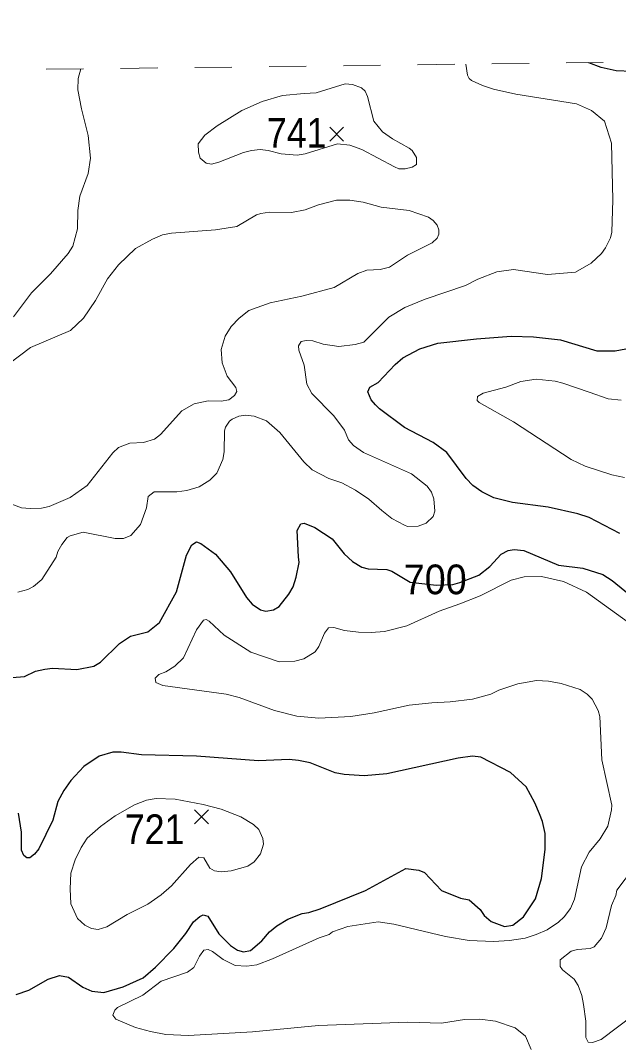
# Model space of a CAD drawing. Extents: x 294.2 to 320.3, y 7482.7 to 7510.7.
# Drawn here: x 309.032 to 310.642, y 7507.992 to 7510.744 of the extents above; entities that cross this region are included whole.
import ezdxf
from ezdxf.enums import TextEntityAlignment as Align

# ---------------------------------------------------------------- set-up
doc = ezdxf.new("R2010")
doc.units = 0
doc.header["$LTSCALE"] = 0.032
doc.linetypes.add('SHORT_DASHED', pattern=[2.7, 1.5, -1.2])
for name, color, linetype, lineweight in [('1', 7, 'Continuous', 25), ('2', 7, 'Continuous', 13), ('21', 7, 'Continuous', 25), ('22', 7, 'SHORT_DASHED', 13)]:
    doc.layers.add(name, color=color, linetype=linetype, lineweight=lineweight)
doc.layers.add('61', color=7, linetype='Continuous')

msp = doc.modelspace()

# ---------------------------------------------------------------- linework, layer by layer
at = {"layer": '1'}
for points in [[(310.7625, 7510.6029), (310.636, 7510.6077), (310.5953, 7510.6168), (310.5623, 7510.63)], [(310.2324, 7509.511), (310.1802, 7509.5804), (310.1436, 7509.6078), (310.066, 7509.6481), (309.9985, 7509.698), (309.9883, 7509.7088), (309.9762, 7509.7222), (309.9677, 7509.7439), (309.973, 7509.7567), (309.9953, 7509.7688), (310.0406, 7509.818), (310.0617, 7509.8359), (310.107, 7509.8601), (310.1562, 7509.8748), (310.2597, 7509.8869), (310.3535, 7509.894), (310.4131, 7509.8922), (310.4858, 7509.8841), (310.5841, 7509.8545), (310.6329, 7509.8545), (310.6623, 7509.8593)], [(310.5325, 7509.4158), (310.4526, 7509.4335), (310.3572, 7509.4459), (310.3062, 7509.4583), (310.274, 7509.4744), (310.2502, 7509.4916), (310.2324, 7509.511)], [(310.6462, 7509.3631), (310.563, 7509.4061), (310.5325, 7509.4158)], [(309.0091, 7508.9747), (309.0429, 7508.978), (309.0723, 7508.9919), (309.0978, 7508.9979), (309.1178, 7509), (309.1838, 7508.9962), (309.2293, 7509.0059), (309.247, 7509.0167), (309.2986, 7509.0667), (309.3286, 7509.086), (309.3751, 7509.0979), (309.4067, 7509.1232), (309.4517, 7509.2059), (309.4788, 7509.3044), (309.4932, 7509.3318), (309.506, 7509.3404), (309.5176, 7509.3361), (309.5575, 7509.307), (309.5974, 7509.2596), (309.6407, 7509.1908), (309.6562, 7509.1725), (309.6779, 7509.1569), (309.6928, 7509.1532), (309.7133, 7509.157), (309.7288, 7509.1666), (309.7549, 7509.1994), (309.7666, 7509.2193), (309.7739, 7509.2448), (309.7822, 7509.2847), (309.781, 7509.2997), (309.7771, 7509.3708), (309.7866, 7509.389), (309.796, 7509.3907), (309.8249, 7509.3788), (309.8709, 7509.348), (309.9037, 7509.3076), (309.9264, 7509.2872), (309.9508, 7509.2721), (309.9685, 7509.2673), (310.0185, 7509.2656), (310.0323, 7509.2613), (310.0811, 7509.2317), (310.1521, 7509.2237), (310.1964, 7509.2258), (310.2147, 7509.2312), (310.2663, 7509.2506), (310.2962, 7509.2737), (310.3261, 7509.307), (310.3456, 7509.3173), (310.3611, 7509.3199), (310.3872, 7509.3167), (310.4805, 7509.2774), (310.546, 7509.2697), (310.6004, 7509.2519), (310.6254, 7509.2358), (310.6935, 7509.1807)], [(309.0204, 7508.1222), (309.0542, 7508.133), (309.1069, 7508.1626), (309.1368, 7508.1733), (309.1612, 7508.1685), (309.1995, 7508.1416), (309.2239, 7508.1303), (309.2561, 7508.1271), (309.3088, 7508.1421), (309.362, 7508.1668), (309.3959, 7508.1953), (309.4447, 7508.2458), (309.4769, 7508.2856), (309.4974, 7508.3173), (309.5146, 7508.3313), (309.524, 7508.3361), (309.5362, 7508.3324), (309.5662, 7508.2851), (309.5972, 7508.2534), (309.6161, 7508.2415), (309.6322, 7508.2362), (309.6516, 7508.2405), (309.6821, 7508.2658), (309.7021, 7508.29), (309.722, 7508.3066), (309.752, 7508.3244), (309.7903, 7508.3395), (309.808, 7508.3421), (309.8385, 7508.3524), (309.9611, 7508.4014), (310.0695, 7508.4607), (310.1045, 7508.4568), (310.12, 7508.4499), (310.1655, 7508.402), (310.2165, 7508.381), (310.2398, 7508.3762), (310.2697, 7508.3509), (310.2808, 7508.3348), (310.2991, 7508.3181), (310.3352, 7508.3052), (310.3579, 7508.3084), (310.3868, 7508.331), (310.4184, 7508.3789), (310.4345, 7508.4343), (310.4451, 7508.5117), (310.4445, 7508.5553), (310.4377, 7508.5878), (310.4299, 7508.6077), (310.4171, 7508.6378), (310.3933, 7508.6809), (310.3512, 7508.7196), (310.2717, 7508.7604), (310.2494, 7508.7631), (310.2106, 7508.7583), (310.0181, 7508.7159), (309.9576, 7508.71), (309.9033, 7508.7138), (309.8789, 7508.7186), (309.8118, 7508.7455), (309.7807, 7508.7514), (309.7552, 7508.7541), (309.6731, 7508.7503), (309.5061, 7508.7632), (309.358, 7508.7669), (309.3031, 7508.7744), (309.2808, 7508.7744), (309.2442, 7508.7632), (309.2021, 7508.7352), (309.1671, 7508.6981), (309.1483, 7508.6712), (309.1328, 7508.6416), (309.1189, 7508.5911), (309.0811, 7508.5142), (309.07, 7508.4992), (309.0573, 7508.49), (309.0489, 7508.49), (309.0406, 7508.4959), (309.0351, 7508.5105), (309.0345, 7508.5584), (309.0262, 7508.61)]]:
    msp.add_lwpolyline(points, dxfattribs=at)
at = {"layer": '2'}
for points in [[(309.0133, 7509.9457), (309.0618, 7510.0108), (309.1129, 7510.0619), (309.1602, 7510.1168), (309.1729, 7510.136), (309.1851, 7510.1826), (309.1864, 7510.2318), (309.1921, 7510.2707), (309.2145, 7510.332), (309.2202, 7510.3729), (309.2145, 7510.4342), (309.1959, 7510.5057), (309.1864, 7510.5567), (309.187, 7510.5874), (309.1942, 7510.6134)], [(310.2314, 7510.626), (310.236, 7510.5963), (310.2405, 7510.5874), (310.2462, 7510.5816), (310.2763, 7510.5689), (310.3056, 7510.5587), (310.3657, 7510.5452), (310.5291, 7510.5191), (310.57, 7510.5012), (310.6044, 7510.4724), (310.623, 7510.4137), (310.6268, 7510.2605), (310.6242, 7510.1737), (310.6204, 7510.1583), (310.6076, 7510.1315), (310.5961, 7510.1162), (310.5687, 7510.09), (310.5265, 7510.0657), (310.4512, 7510.0594), (310.3593, 7510.0734), (310.3146, 7510.067), (310.2635, 7510.0472), (310.2303, 7510.0306), (310.1218, 7509.9936), (310.0668, 7509.9712), (310.0234, 7509.9451), (309.9564, 7509.8774), (309.9328, 7509.871), (309.8894, 7509.8659), (309.8472, 7509.8723), (309.8191, 7509.8812), (309.8012, 7509.8825), (309.7878, 7509.8799), (309.7802, 7509.8678), (309.7814, 7509.8563), (309.7955, 7509.8161), (309.8031, 7509.765), (309.8165, 7509.7395), (309.8759, 7509.6795), (309.904, 7509.6412), (309.9149, 7509.6144), (309.9289, 7509.5996), (309.9558, 7509.5805), (310.0847, 7509.523), (310.1268, 7509.4905), (310.1383, 7509.4739), (310.1454, 7509.456), (310.1479, 7509.4228), (310.1428, 7509.4087), (310.1243, 7509.3902), (310.1026, 7509.3826), (310.0745, 7509.3819), (310.0656, 7509.3851), (310.0317, 7509.403), (310.0049, 7509.4247), (309.9698, 7509.4547), (309.934, 7509.4796), (309.897, 7509.4988), (309.8625, 7509.5103), (309.8178, 7509.5339), (309.7948, 7509.5556), (309.7304, 7509.6341), (309.694, 7509.6661), (309.6608, 7509.6782), (309.6378, 7509.6814), (309.6199, 7509.6788), (309.602, 7509.6705), (309.595, 7509.6654), (309.5841, 7509.6488), (309.581, 7509.6392), (309.5803, 7509.5824), (309.5765, 7509.562), (309.5605, 7509.5249), (309.5414, 7509.5064), (309.5127, 7509.4886), (309.4795, 7509.4783), (309.4526, 7509.4745), (309.3919, 7509.4745), (309.376, 7509.4624), (309.3715, 7509.4317), (309.3549, 7509.3871), (309.3288, 7509.357), (309.309, 7509.3494), (309.2866, 7509.3494), (309.2011, 7509.366), (309.1653, 7509.3564), (309.1576, 7509.3519), (309.1429, 7509.3334), (309.1321, 7509.3142), (309.1276, 7509.2989), (309.0893, 7509.2389), (309.067, 7509.2197), (309.0517, 7509.2115), (309.0249, 7509.2044)], [(308.9687, 7509.7963), (309.0593, 7509.8633), (309.1666, 7509.9093), (309.2017, 7509.9425), (309.2342, 7509.9898), (309.2662, 7510.0478), (309.2955, 7510.0862), (309.3414, 7510.1301), (309.3874, 7510.1551), (309.4143, 7510.1666), (309.4386, 7510.1711), (309.5573, 7510.18), (309.6141, 7510.189), (309.6672, 7510.2202), (309.6787, 7510.2241), (309.7029, 7510.2273), (309.7617, 7510.2266), (309.7987, 7510.2336), (309.8344, 7510.2471), (309.883, 7510.2598), (309.9187, 7510.2598), (309.9545, 7510.2541), (310.003, 7510.2407), (310.0783, 7510.2318), (310.1307, 7510.2139), (310.1435, 7510.2056), (310.1537, 7510.1928), (310.1588, 7510.18), (310.1588, 7510.1685), (310.1543, 7510.1577), (310.1409, 7510.1455), (310.0745, 7510.1117), (310.026, 7510.0798), (310.0005, 7510.0734), (309.9647, 7510.0715), (309.9404, 7510.0625), (309.8766, 7510.0249), (309.7898, 7510.0019), (309.7042, 7509.984), (309.6467, 7509.9629), (309.6206, 7509.9425), (309.5995, 7509.9195), (309.5835, 7509.894), (309.5726, 7509.8583), (309.5746, 7509.8225), (309.5886, 7509.7861), (309.6116, 7509.7561), (309.6148, 7509.7446), (309.6084, 7509.7344), (309.5931, 7509.7229), (309.5727, 7509.719), (309.5369, 7509.7197), (309.4999, 7509.712), (309.4667, 7509.6929), (309.4092, 7509.629), (309.3926, 7509.6169), (309.3633, 7509.6079), (309.3262, 7509.606), (309.2962, 7509.5939), (309.2809, 7509.5799), (309.2113, 7509.4917), (309.1659, 7509.4592), (309.1091, 7509.4355), (309.0887, 7509.4311), (309.0581, 7509.4298), (309.0347, 7509.4317), (309.0088, 7509.442)], [(310.6491, 7509.7216), (310.6147, 7509.7248), (310.5636, 7509.7427), (310.4921, 7509.7676), (310.4716, 7509.7726), (310.4206, 7509.7778), (310.3797, 7509.7714), (310.3388, 7509.7567), (310.2776, 7509.7401), (310.2628, 7509.7312), (310.2616, 7509.7209), (310.2667, 7509.7152), (310.3593, 7509.6635), (310.515, 7509.562), (310.5521, 7509.5435), (310.624, 7509.5205), (310.6581, 7509.5134)], [(310.6696, 7509.1234), (310.5559, 7509.2051), (310.4946, 7509.2332), (310.4346, 7509.2472), (310.3886, 7509.2459), (310.3529, 7509.237), (310.2699, 7509.1949), (310.215, 7509.1732), (310.1594, 7509.1533), (310.072, 7509.1144), (310.0119, 7509.0991), (309.9762, 7509.0959), (309.9417, 7509.0972), (309.9047, 7509.1016), (309.8759, 7509.1093), (309.8612, 7509.1086), (309.8504, 7509.0946), (309.8351, 7509.0589), (309.8255, 7509.0442), (309.7949, 7509.025), (309.7706, 7509.0186), (309.7285, 7509.0174), (309.6518, 7509.0429), (309.5803, 7509.0889), (309.5401, 7509.1265), (309.5318, 7509.131), (309.5247, 7509.1297), (309.5062, 7509.1036), (309.4711, 7509.0282), (309.4475, 7509.0052), (309.4233, 7508.9906), (309.4041, 7508.9829), (309.3945, 7508.9733), (309.3964, 7508.9618), (309.4156, 7508.9535), (309.5854, 7508.9305), (309.6212, 7508.9209), (309.7157, 7508.8864), (309.7757, 7508.8711), (309.8357, 7508.866), (309.9213, 7508.8698), (309.9839, 7508.8795), (310.0783, 7508.9005), (310.1396, 7508.9069), (310.1894, 7508.9094), (310.2495, 7508.9171), (310.2986, 7508.9305), (310.3197, 7508.9408), (310.3708, 7508.958), (310.4218, 7508.9669), (310.4538, 7508.9656), (310.4882, 7508.9592), (310.5387, 7508.9426), (310.5578, 7508.9305), (310.5712, 7508.9171), (310.5872, 7508.8865), (310.5917, 7508.8705), (310.5974, 7508.7537), (310.6243, 7508.6317), (310.6238, 7508.6184), (310.6133, 7508.5749), (310.5929, 7508.5411), (310.5635, 7508.5047), (310.5425, 7508.4651), (310.524, 7508.3783), (310.5131, 7508.3533), (310.4959, 7508.3304), (310.4806, 7508.3169), (310.4499, 7508.2959), (310.4206, 7508.2831), (310.3912, 7508.2735), (310.3491, 7508.2671), (310.3056, 7508.264), (310.2405, 7508.2671), (310.1767, 7508.278), (310.0375, 7508.3112), (309.9949, 7508.3176), (309.9134, 7508.3045), (309.8721, 7508.2901), (309.8629, 7508.2831)], [(310.6836, 7508.0673), (310.5955, 7508.0009), (310.5725, 7507.9926), (310.5604, 7507.9932), (310.554, 7508.006), (310.554, 7508.0501), (310.5482, 7508.0948), (310.5438, 7508.119), (310.5336, 7508.1459), (310.5227, 7508.1631), (310.4914, 7508.1886), (310.485, 7508.1975), (310.485, 7508.2154), (310.5144, 7508.2384), (310.5317, 7508.2429), (310.5661, 7508.2454), (310.577, 7508.2505), (310.5961, 7508.2735), (310.6089, 7508.3016), (310.6236, 7508.361), (310.6351, 7508.3885), (310.6376, 7508.4025), (310.7673, 7508.573)], [(309.8629, 7508.2831), (309.8365, 7508.2742), (309.7106, 7508.218), (309.6684, 7508.202), (309.6416, 7508.1976), (309.61, 7508.2), (309.5778, 7508.2162)], [(309.5778, 7508.2162), (309.5491, 7508.2379), (309.5376, 7508.2429), (309.5261, 7508.241), (309.5139, 7508.225), (309.4986, 7508.1943), (309.482, 7508.1822), (309.4111, 7508.1573), (309.3613, 7508.1196), (309.2931, 7508.0869), (309.2856, 7508.0796), (309.281, 7508.0657), (309.2885, 7508.0552), (309.3415, 7508.0328), (309.3824, 7508.0219), (309.4233, 7508.0143), (309.4846, 7508.0111), (309.657, 7508.0213), (309.8344, 7508.0379), (310.0754, 7508.047), (310.1652, 7508.0449), (310.2278, 7508.0545), (310.2686, 7508.0558), (310.3108, 7508.05), (310.3644, 7508.0316), (310.3918, 7508.0098), (310.4072, 7507.9735)]]:
    msp.add_lwpolyline(points, dxfattribs=at)
for points in [[(309.7961, 7510.5471), (309.7374, 7510.5421), (309.6825, 7510.5255), (309.6276, 7510.5012), (309.5612, 7510.4603), (309.5286, 7510.4348), (309.5107, 7510.4112), (309.5113, 7510.3895), (309.5158, 7510.3729), (309.5318, 7510.3594), (309.5459, 7510.3569), (309.5663, 7510.362), (309.6327, 7510.3881), (309.6544, 7510.3932), (309.6774, 7510.3965), (309.6991, 7510.3939), (309.7336, 7510.3843), (309.777, 7510.3812), (309.7987, 7510.385), (309.8855, 7510.4118), (309.9189, 7510.4081), (309.9507, 7510.3965), (310.0388, 7510.3498), (310.0509, 7510.3447), (310.0681, 7510.3441), (310.0866, 7510.3486), (310.0987, 7510.3562), (310.0987, 7510.3748), (310.0866, 7510.3933), (310.0783, 7510.4003), (310.0337, 7510.4252), (310.0068, 7510.4437), (309.9838, 7510.4725), (309.9666, 7510.5389), (309.9602, 7510.5529), (309.9506, 7510.5625), (309.9264, 7510.5714), (309.906, 7510.5733), (309.8281, 7510.5484)], [(309.5241, 7508.6329), (309.4488, 7508.6477), (309.3977, 7508.6489), (309.3709, 7508.6445), (309.339, 7508.6323), (309.2866, 7508.6024), (309.247, 7508.5736), (309.2119, 7508.543), (309.1953, 7508.5174), (309.1793, 7508.4842), (309.1678, 7508.4485), (309.1653, 7508.4064), (309.1678, 7508.3655), (309.1851, 7508.3259), (309.2055, 7508.3087), (309.2228, 7508.2997), (309.2407, 7508.2965), (309.2649, 7508.3042), (309.3192, 7508.3368), (309.3753, 7508.3648), (309.4111, 7508.3904), (309.4386, 7508.414), (309.4896, 7508.4715), (309.5126, 7508.4913), (309.5254, 7508.4893), (309.542, 7508.4619), (309.5541, 7508.4548), (309.5727, 7508.4517), (309.5995, 7508.4548), (309.6442, 7508.4676), (309.6614, 7508.4785), (309.678, 7508.5008), (309.6863, 7508.5264), (309.6844, 7508.5417), (309.6735, 7508.566), (309.6595, 7508.5794), (309.625, 7508.6004), (309.5727, 7508.6202)]]:
    msp.add_lwpolyline(points, close=True, dxfattribs=at)
at = {"layer": '21'}
for p, q in [((309.8646, 7510.456), (309.9021, 7510.4185)), ((309.9021, 7510.456), (309.8646, 7510.4185)), ((309.5003, 7508.6184), (309.5378, 7508.5809)), ((309.5378, 7508.6184), (309.5003, 7508.5809))]:
    msp.add_line(p, q, dxfattribs=at)
at = {"layer": '22'}
msp.add_lwpolyline([(294.2515, 7510.4214), (307.9016, 7510.5978), (319.9762, 7510.7437)], dxfattribs=at)

# ---------------------------------------------------------------- texts
at = {"layer": '61'}
for s, width, p in [('741', 0.9, (309.7758, 7510.4012)), ('700', 0.95, (310.1487, 7509.1991)), ('721', 0.9, (309.3931, 7508.5266))]:
    msp.add_text(s, height=0.08, dxfattribs=dict(at, width=width)).set_placement(p, align=Align.CENTER)

doc.saveas('drawing.dxf')
